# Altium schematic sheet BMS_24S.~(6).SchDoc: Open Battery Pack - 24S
size A3; Date: 26/03/2019; Author: Morgane Vallée - Samuel Lesueur; Revision: 1.0; SheetNumber: 1; SheetTotal: 2
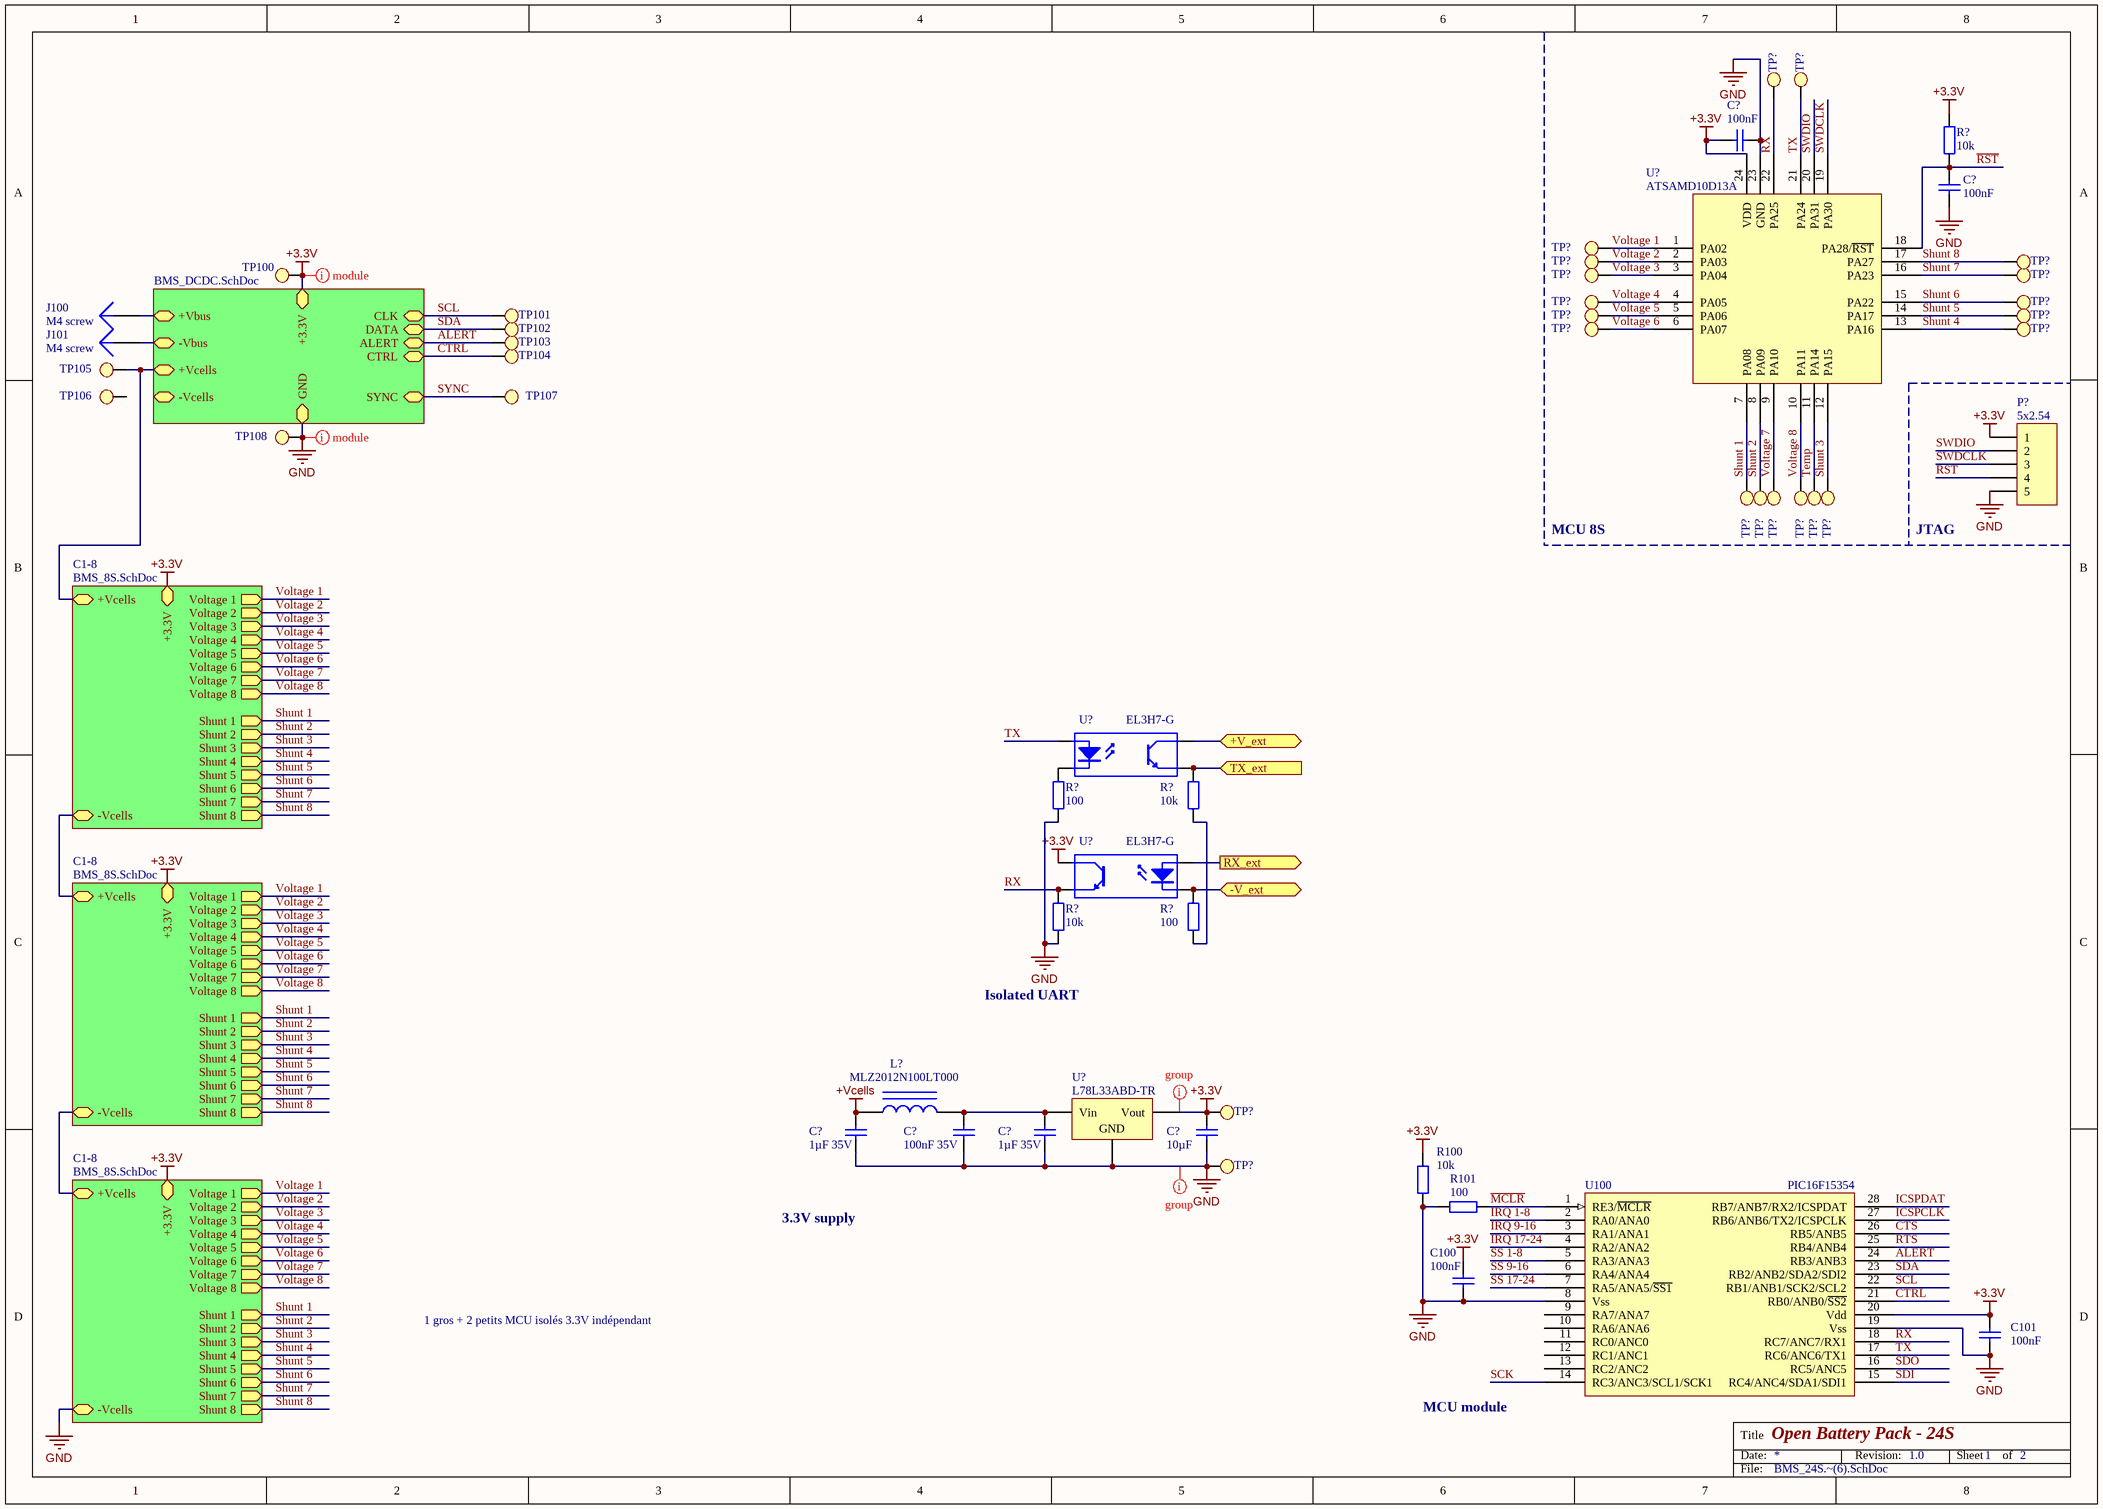
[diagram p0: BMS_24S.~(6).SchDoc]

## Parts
(Parts that share a designator on the sheet are numbered #1, #2 ... from top to bottom, then left to right.)
C100  100nF  [C0603]
C101  100nF  [C0603]
C?#1  100nF  [C0603]
C?#2  100nF  [C0603]
C?#3  1µF 35V  [C0805]
C?#4  100nF 35V  [C0603]
C?#5  1µF 35V  [C0805]
C?#6  10µF  [C0603]
J100  M4 screw  [HOLE_4]
J101  M4 screw  [HOLE_4]
L?  MLZ2012N100LT000  [FER 0805/2012]
P?  5x2.54  [HDR1X5]
R100  10k  [R0603]
R101  100  [R0603]
R?#1  10k  [R0603]
R?#2  10k  [R0603]
R?#3  100  [R0603]
R?#4  100  [R0603]
R?#5  10k  [R0603]
TP100  Test Point  [Test Point]  (value not drawn)
TP101  Test Point  [Test Point]  (value not drawn)
TP102  Test Point  [Test Point]  (value not drawn)
TP103  Test Point  [Test Point]  (value not drawn)
TP104  Test Point  [Test Point]  (value not drawn)
TP105  Test Point  [Test Point]  (value not drawn)
TP106  Test Point  [Test Point]  (value not drawn)
TP107  Test Point  [Test Point]  (value not drawn)
TP108  Test Point  [Test Point]  (value not drawn)
TP?#1  Test Point  [Test Point]  (value not drawn)
TP?#2  Test Point  [Test Point]  (value not drawn)
TP?#3  Test Point  [Test Point]  (value not drawn)
TP?#4  Test Point  [Test Point]  (value not drawn)
TP?#5  Test Point  [Test Point]  (value not drawn)
TP?#6  Test Point  [Test Point]  (value not drawn)
TP?#7  Test Point  [Test Point]  (value not drawn)
TP?#8  Test Point  [Test Point]  (value not drawn)
TP?#9  Test Point  [Test Point]  (value not drawn)
TP?#10  Test Point  [Test Point]  (value not drawn)
TP?#11  Test Point  [Test Point]  (value not drawn)
TP?#12  Test Point  [Test Point]  (value not drawn)
TP?#13  Test Point  [Test Point]  (value not drawn)
TP?#14  Test Point  [Test Point]  (value not drawn)
TP?#15  Test Point  [Test Point]  (value not drawn)
TP?#16  Test Point  [Test Point]  (value not drawn)
TP?#17  Test Point  [Test Point]  (value not drawn)
TP?#18  Test Point  [Test Point]  (value not drawn)
TP?#19  Test Point  [Test Point]  (value not drawn)
TP?#20  Test Point  [Test Point]  (value not drawn)
TP?#21  Test Point  [Test Point]  (value not drawn)
U100  PIC16F15354  [SSOP_28]
U?#1  ATSAMD10D13A  [SMSC QFN-24 4x4MM]
U?#2  EL3H7-G  [OPTO_EL3H7-G]
U?#3  EL3H7-G  [OPTO_EL3H7-G]
U?#4  L78L33ABD-TR  [ST SOIC-8N]

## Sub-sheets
C1-8 = BMS_8S.SchDoc: Voltage 6 (out), Shunt 2 (out), Shunt 7 (out), Shunt 6 (out), Voltage 3 (out), Voltage 5 (out), Shunt 8 (out), Voltage 8 (out), Voltage 7 (out), +3.3V, Voltage 2 (out), Shunt 4 (out), Shunt 3 (out), Shunt 5 (out), Voltage 4 (out), -Vcells, +Vcells, Shunt 1 (out), Voltage 1 (out)
C1-8 = BMS_8S.SchDoc: Voltage 6 (out), Shunt 2 (out), Shunt 7 (out), Shunt 6 (out), Voltage 3 (out), Voltage 5 (out), Shunt 8 (out), Voltage 8 (out), Voltage 7 (out), +3.3V, Voltage 2 (out), Shunt 4 (out), Shunt 3 (out), Shunt 5 (out), Voltage 4 (out), -Vcells, +Vcells, Shunt 1 (out), Voltage 1 (out)
C1-8 = BMS_8S.SchDoc: Voltage 6 (out), Shunt 2 (out), Shunt 7 (out), Shunt 6 (out), Voltage 3 (out), Voltage 5 (out), Shunt 8 (out), Voltage 8 (out), Voltage 7 (out), +3.3V, Voltage 2 (out), Shunt 4 (out), Shunt 3 (out), Shunt 5 (out), Voltage 4 (out), -Vcells, +Vcells, Shunt 1 (out), Voltage 1 (out)
? = BMS_DCDC.SchDoc: CTRL (bidir), SYNC (bidir), CLK (bidir), DATA (bidir), ALERT (bidir), GND, +3.3V, -Vbus, +Vbus, -Vcells, +Vcells

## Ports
+V_ext, -V_ext, RX_ext (out), TX_ext (in)

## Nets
+3.3V: C100.2 C101.2 C?#1.2 C?#6.1 P?.1 R100.2 R?#1.2 TP100.1 TP?#20.1 U100.20(Vdd) U?#1.24(VDD) U?#3.4(C) U?#4.3(Vout) ; sheet /+3.3V, sheet C1-8/+3.3V, sheet C1-8/+3.3V, sheet C1-8/+3.3V
+Vcells: C?#3.1 L?.1
GND: C100.1 C101.1 C?#1.1 C?#2.1 C?#3.2 C?#4.2 C?#5.2 C?#6.2 P?.5 R100.1 R101.2 R?#3.1 R?#5.1 TP108.1 TP?#21.1 U100.8(Vss) U100.19(Vss) U?#1.23(GND) U?#4.2(GND) ; sheet /GND, sheet C1-8/-Vcells
+V_ext: U?#2.4(C) ; port +V_ext
-V_ext: R?#4.1 U?#3.2(K) ; port -V_ext
ALERT: TP103.1 U100.24(RB3/ANB3) ; sheet /ALERT
CTRL: TP104.1 U100.21(RB0/ANB0/~{SS2}) ; sheet /CTRL
CTS: U100.26(RB5/ANB5)
ICSPCLK: U100.27(RB6/ANB6/TX2/ICSPCLK)
ICSPDAT: U100.28(RB7/ANB7/RX2/ICSPDAT)
IRQ 1-8: U100.2(RA0/ANA0)
IRQ 9-16: U100.3(RA1/ANA1)
IRQ 17-24: U100.4(RA2/ANA2)
~{MCLR}: R101.1 U100.1(RE3/~{MCLR})
~{RST}: C?#2.2 P?.4 R?#1.1 U?#1.18(PA28/~{RST})
RTS: U100.25(RB4/ANB4)
RX: R?#5.2 TP?#1.1 U100.18(RC7/ANC7/RX1) U?#1.22(PA25) U?#3.3(E)
RX_ext: U?#3.1(A) ; port RX_ext
~{SS} 1-8: U100.5(RA3/ANA3)
~{SS} 9-16: U100.6(RA4/ANA4)
~{SS} 17-24: U100.7(RA5/ANA5/~{SS1})
SCK: U100.14(RC3/ANC3/SCL1/SCK1)
SCL: TP101.1 U100.22(RB1/ANB1/SCK2/SCL2) ; sheet /CLK
SDA: TP102.1 U100.23(RB2/ANB2/SDA2/SDI2) ; sheet /DATA
SDI: U100.15(RC4/ANC4/SDA1/SDI1)
SDO: U100.16(RC5/ANC5)
Shunt 1: TP?#14.1 U?#1.7(PA08) ; sheet C1-8/Shunt 1, sheet C1-8/Shunt 1, sheet C1-8/Shunt 1
Shunt 2: TP?#15.1 U?#1.8(PA09) ; sheet C1-8/Shunt 2, sheet C1-8/Shunt 2, sheet C1-8/Shunt 2
Shunt 3: TP?#19.1 U?#1.12(PA15) ; sheet C1-8/Shunt 3, sheet C1-8/Shunt 3, sheet C1-8/Shunt 3
Shunt 4: TP?#13.1 U?#1.13(PA16) ; sheet C1-8/Shunt 4, sheet C1-8/Shunt 4, sheet C1-8/Shunt 4
Shunt 5: TP?#11.1 U?#1.14(PA17) ; sheet C1-8/Shunt 5, sheet C1-8/Shunt 5, sheet C1-8/Shunt 5
Shunt 6: TP?#9.1 U?#1.15(PA22) ; sheet C1-8/Shunt 6, sheet C1-8/Shunt 6, sheet C1-8/Shunt 6
Shunt 7: TP?#7.1 U?#1.16(PA23) ; sheet C1-8/Shunt 7, sheet C1-8/Shunt 7, sheet C1-8/Shunt 7
Shunt 8: TP?#5.1 U?#1.17(PA27) ; sheet C1-8/Shunt 8, sheet C1-8/Shunt 8, sheet C1-8/Shunt 8
SWDCLK: P?.3 U?#1.19(PA30)
SWDIO: P?.2 U?#1.20(PA31)
SYNC: TP107.1 ; sheet /SYNC
Temp: TP?#18.1 U?#1.11(PA14)
TX: TP?#2.1 U100.17(RC6/ANC6/TX1) U?#1.21(PA24) U?#2.1(A)
TX_ext: R?#2.1 U?#2.3(E) ; port TX_ext
Voltage 1: TP?#3.1 U?#1.1(PA02) ; sheet C1-8/Voltage 1, sheet C1-8/Voltage 1, sheet C1-8/Voltage 1
Voltage 2: TP?#4.1 U?#1.2(PA03) ; sheet C1-8/Voltage 2, sheet C1-8/Voltage 2, sheet C1-8/Voltage 2
Voltage 3: TP?#6.1 U?#1.3(PA04) ; sheet C1-8/Voltage 3, sheet C1-8/Voltage 3, sheet C1-8/Voltage 3
Voltage 4: TP?#8.1 U?#1.4(PA05) ; sheet C1-8/Voltage 4, sheet C1-8/Voltage 4, sheet C1-8/Voltage 4
Voltage 5: TP?#10.1 U?#1.5(PA06) ; sheet C1-8/Voltage 5, sheet C1-8/Voltage 5, sheet C1-8/Voltage 5
Voltage 6: TP?#12.1 U?#1.6(PA07) ; sheet C1-8/Voltage 6, sheet C1-8/Voltage 6, sheet C1-8/Voltage 6
Voltage 7: TP?#16.1 U?#1.9(PA10) ; sheet C1-8/Voltage 7, sheet C1-8/Voltage 7, sheet C1-8/Voltage 7
Voltage 8: TP?#17.1 U?#1.10(PA11) ; sheet C1-8/Voltage 8, sheet C1-8/Voltage 8, sheet C1-8/Voltage 8
NetC?#4_1: C?#4.1 C?#5.1 L?.2 U?#4.1(Vin)
NetJ100_1: J100.1 ; sheet /+Vbus
NetJ101_1: J101.1 ; sheet /-Vbus
NetR?#2_2: R?#2.2 R?#4.2
NetR?#3_2: R?#3.2 U?#2.2(K)
NetTP105_1: TP105.1 ; sheet /+Vcells, sheet C1-8/+Vcells
(unnamed): sheet C1-8/+Vcells, sheet C1-8/-Vcells
(unnamed): sheet C1-8/+Vcells, sheet C1-8/-Vcells  [a separate net that carries the same name]

Not connected (* = marked no-connect by the designer): TP106 1; U100 9(RA7/ANA7) 10(RA6/ANA6) 11(RC0/ANC0) 12(RC1/ANC1) 13(RC2/ANC2)

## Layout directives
net class module: +3.3V, GND
net class Group: +3.3V, GND

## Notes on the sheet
- MCU 8S
- JTAG
- Isolated UART
- 3.3V supply
- 1 gros + 2 petits MCU isolés 3.3V indépendant
- MCU module

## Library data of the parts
C100 C101 C?#1-C?#6 = Cap: Capacitor
J100 J101 = Plug
L? = Inductor Iron: Magnetic-Core Inductor
P? = Header 5: Header, 5-Pin
R100 R101 R?#1-R?#5 = Res2: Resistor
U?#2 U?#3 = Optoisolator1: 4-Pin Phototransistor Optocoupler
U?#4 = Volt Reg: Voltage Regulator; pin to pad: 1>8 2>2+3+6+7 3>1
